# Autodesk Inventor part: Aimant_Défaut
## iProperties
Shininess: 64.0
Length Units: 11269
Angle Units: 11279
Time Units: 11290
Mass Units: 11283
Length Display Precision: 3
Angle Display Precision: 2
Compacted: True
Part Number: Aimant_Défaut
Document SubType Name: Modeling
Created: 2006-01
Material: Par défaut
Designer: Fricot
Density: 0.0
Volumn: 0.0
Area: 0.0
PropertySet Name: Model Information
Control State: 0
Master: False
Checked Out: False
Author: Fricot
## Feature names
1. Base1
